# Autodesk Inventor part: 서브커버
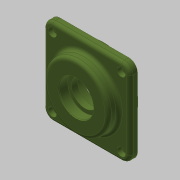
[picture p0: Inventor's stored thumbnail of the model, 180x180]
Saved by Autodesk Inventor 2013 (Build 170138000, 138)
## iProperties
Created: 2018-09
Part Number: 서브커버
Material: 일반
Document SubType Name: Modeling
Designer: mduedu
Density: 1 g/cm^3
Mass: 76.2032 g
Surface Area: 197.007 cm^2
Volume: 76.2032 cm^3
Author: mduedu
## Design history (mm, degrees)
sketch "스케치1"
  geometry: L1 (-40, -40)-(40, -40); L2 (40, -40)-(40, 40); L3 (40, 40)-(-40, 40); L4 (-40, 40)-(-40, -40); L5 (-40, -40)-(40, 40); L6 (40, -40)-(-40, 40); 1 further point
  constraints: 12 end point, 2 midpoint, 2 parallel, 1 horizontal, 1 perpendicular
  dimensions: "d0" = 80 distance of L3.end L2.end; "d1" = 80 distance of L2.end L1.end
extrude "돌출1" new body sketch "스케치1" distance "d2" = 7; taper "d3" = 0 deg
sketch "스케치2"
  geometry: C1 r 30 at (0, 0); 1 further point
  constraints: 1 centre point, 1 coincident
  dimensions: "d4" = 60 diameter of C1
extrude "돌출2" join sketch "스케치2" distance "d5" = 10; taper "d6" = 0 deg
sketch "스케치3"
  geometry: C1 r 32.5 at (0, 0); 1 further point
  constraints: 1 centre point, 1 coincident
  dimensions: "d7" = 65 diameter of C1
extrude "돌출3" join sketch "스케치3" distance "d8" = 9; taper "d9" = 0 deg
sketch "스케치4"
  geometry: L1 (-32.5, -9)-(32.5, -9) reference; L2 (30, 17)-(-30, 17) reference; L3 (0, 17)-(0, -9); L4 (0, -9)-(20, -9); L5 (20, -9)-(20, 3); L6 (20, 3)-(0, 3); L7 (0, 3)-(0, -9); L8 (0, 3)-(12.5, 3); L9 (12.5, 3)-(12.5, 8.7); L10 (12.5, 8.7)-(0, 8.7); L11 (0, 8.7)-(0, 3); L12 (0, 8.7)-(16, 8.7); L13 (16, 8.7)-(16, 17); L14 (16, 17)-(0, 17); L15 (0, 17)-(0, 8.7); 1 further point
  constraints: 26 end point, 6 parallel, 3 horizontal, 3 perpendicular, 2 midpoint, 1 point on line
  dimensions: "d10" = 12 distance of L4.end L5.end; "d12" = 8.3 distance of L12.end L13.end; "d13" = 32 diameter of L13 L3; "d14" = 25 diameter of L9 L3; "d15" = 40 diameter of L5 L3
revolve "회전1" sketch "스케치4" stored, may be unused: angle "d16" = 90 deg
fillet "모깎기1" dims "d17" = 8
fillet "모깎기2" dims "d18" = 3
fillet "모깎기3" dims "d19" = 3
chamfer "모따기1" distance "d20" = 0.8; stored, may be unused: second distance "d21" = 2, angle "d22" = 30 deg
chamfer "모따기2" distance "d23" = 1; stored, may be unused: second distance "d24" = 2, angle "d25" = 30 deg
fillet "모깎기4" dims "d26" = 0.3
sketch "스케치5"
  geometry: A1 r 8 centre (-32, 32) between (-32, 40) and (-40, 32) reference; A2 r 8 centre (-32, -32) between (-40, -32) and (-32, -40) reference; A3 r 8 centre (32, -32) between (32, -40) and (40, -32) reference; A4 r 8 centre (32, 32) between (40, 32) and (32, 40) reference; 5 further points
  constraints: 4 coincident
hole "구멍1" sketch "스케치5" at (-32, 32), (32, 32), (32, -32), (-32, -32) diameter "d27" = 4.5; stored, may be unused: countersink angle "d31" = 90 deg, drill point angle "d33" = 118 deg; dims "d28" = 6, "d29" = 8, "d30" = 4.4, "d32" = 8
node "솔리드1"
